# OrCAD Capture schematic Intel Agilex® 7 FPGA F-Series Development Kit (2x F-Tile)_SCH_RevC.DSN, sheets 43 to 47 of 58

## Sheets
43 PG47 VCC Phase 1: size C
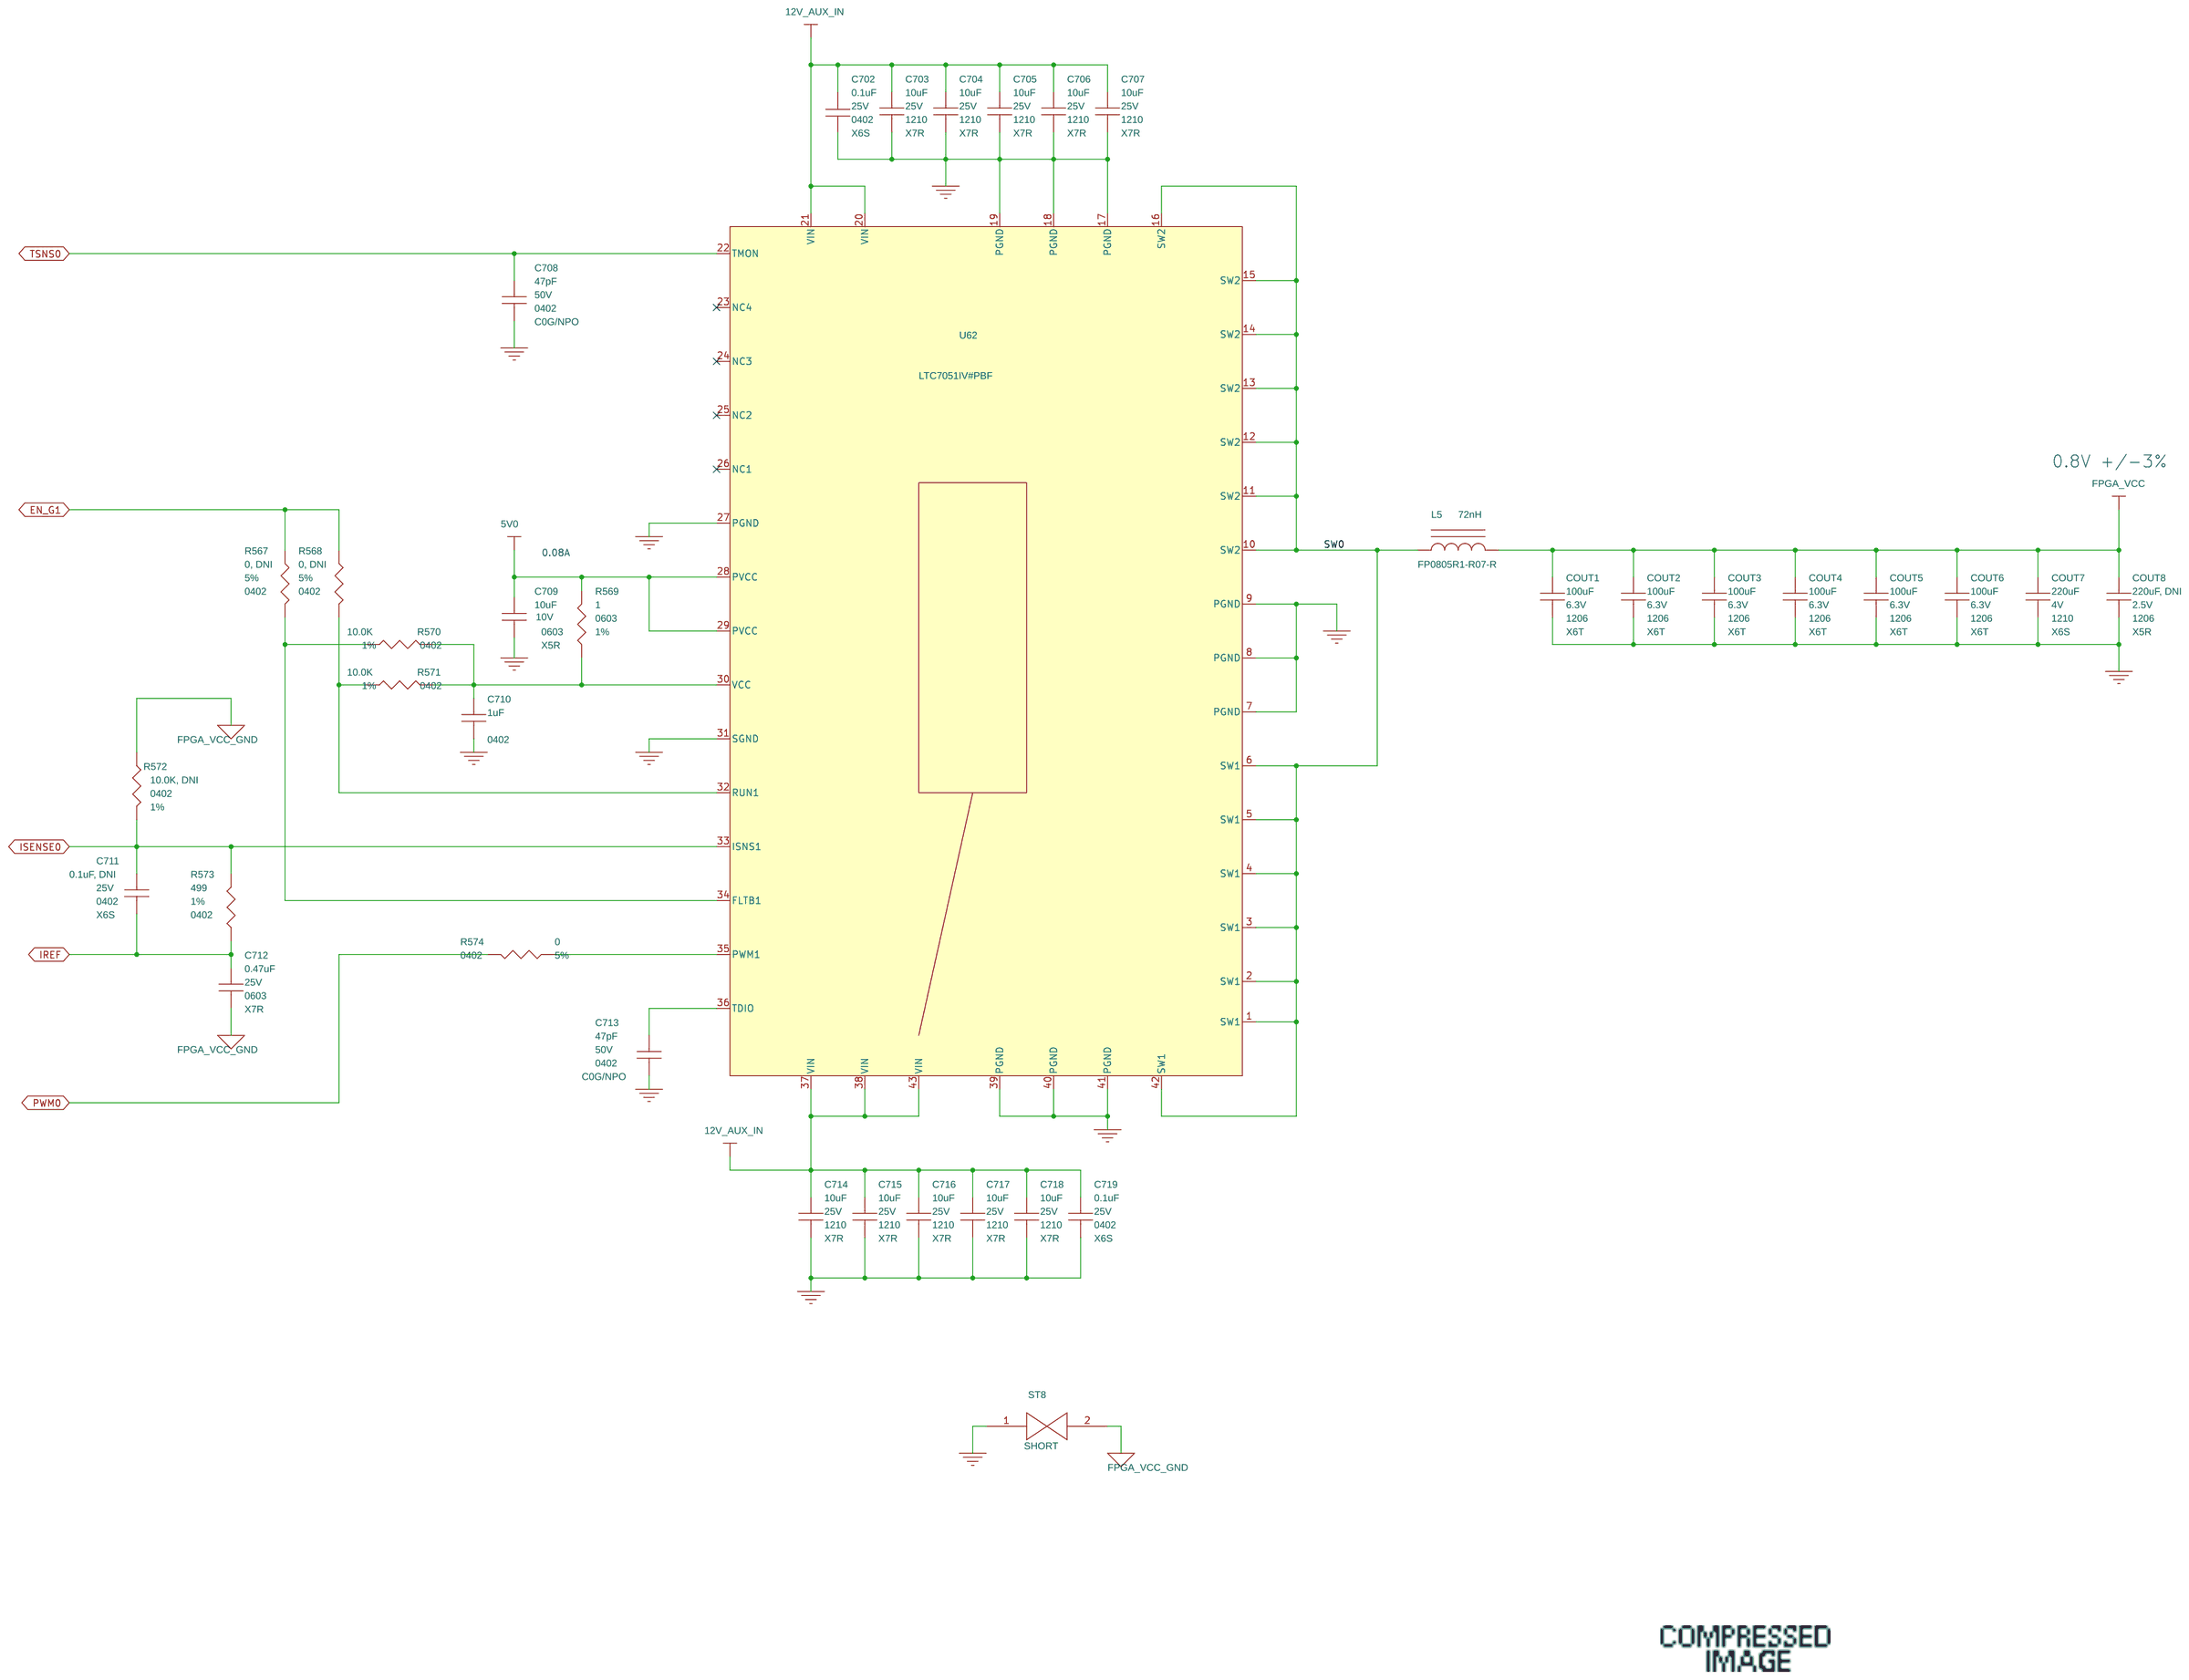
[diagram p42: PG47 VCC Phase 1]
44 PG48 VCC Phase 2: size C
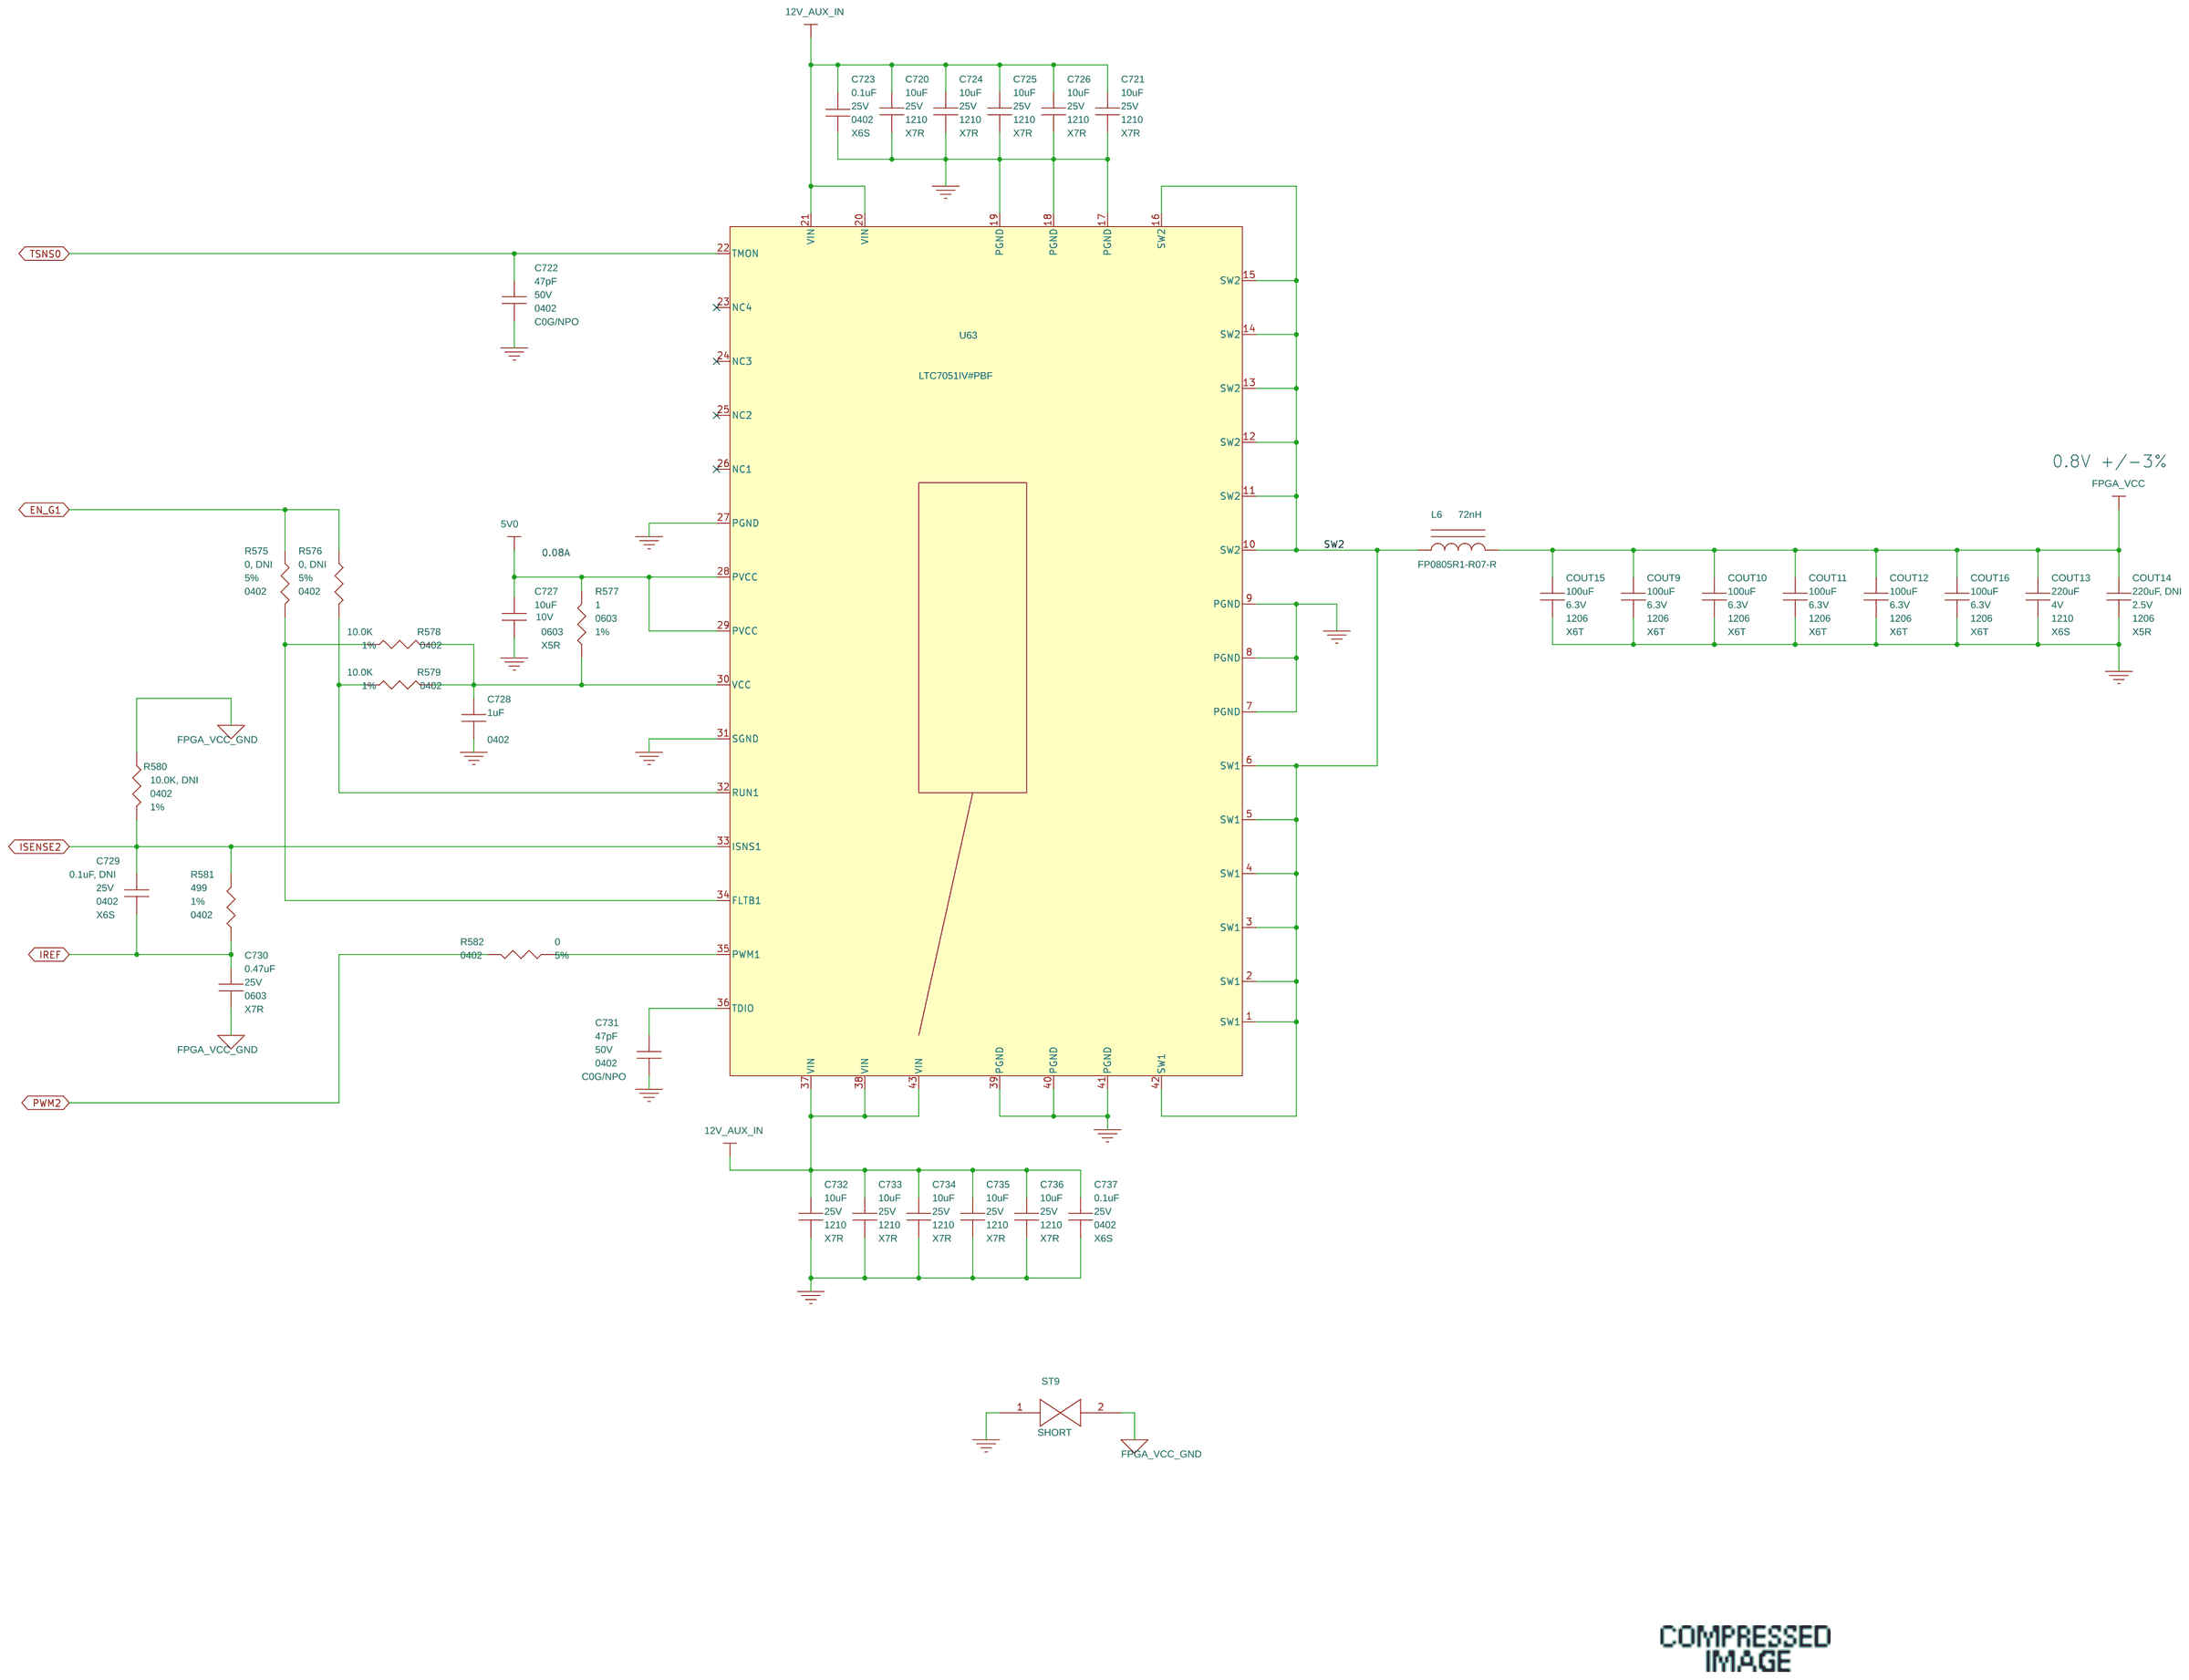
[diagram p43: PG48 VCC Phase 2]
45 PG49 VCC Phase 3: size C
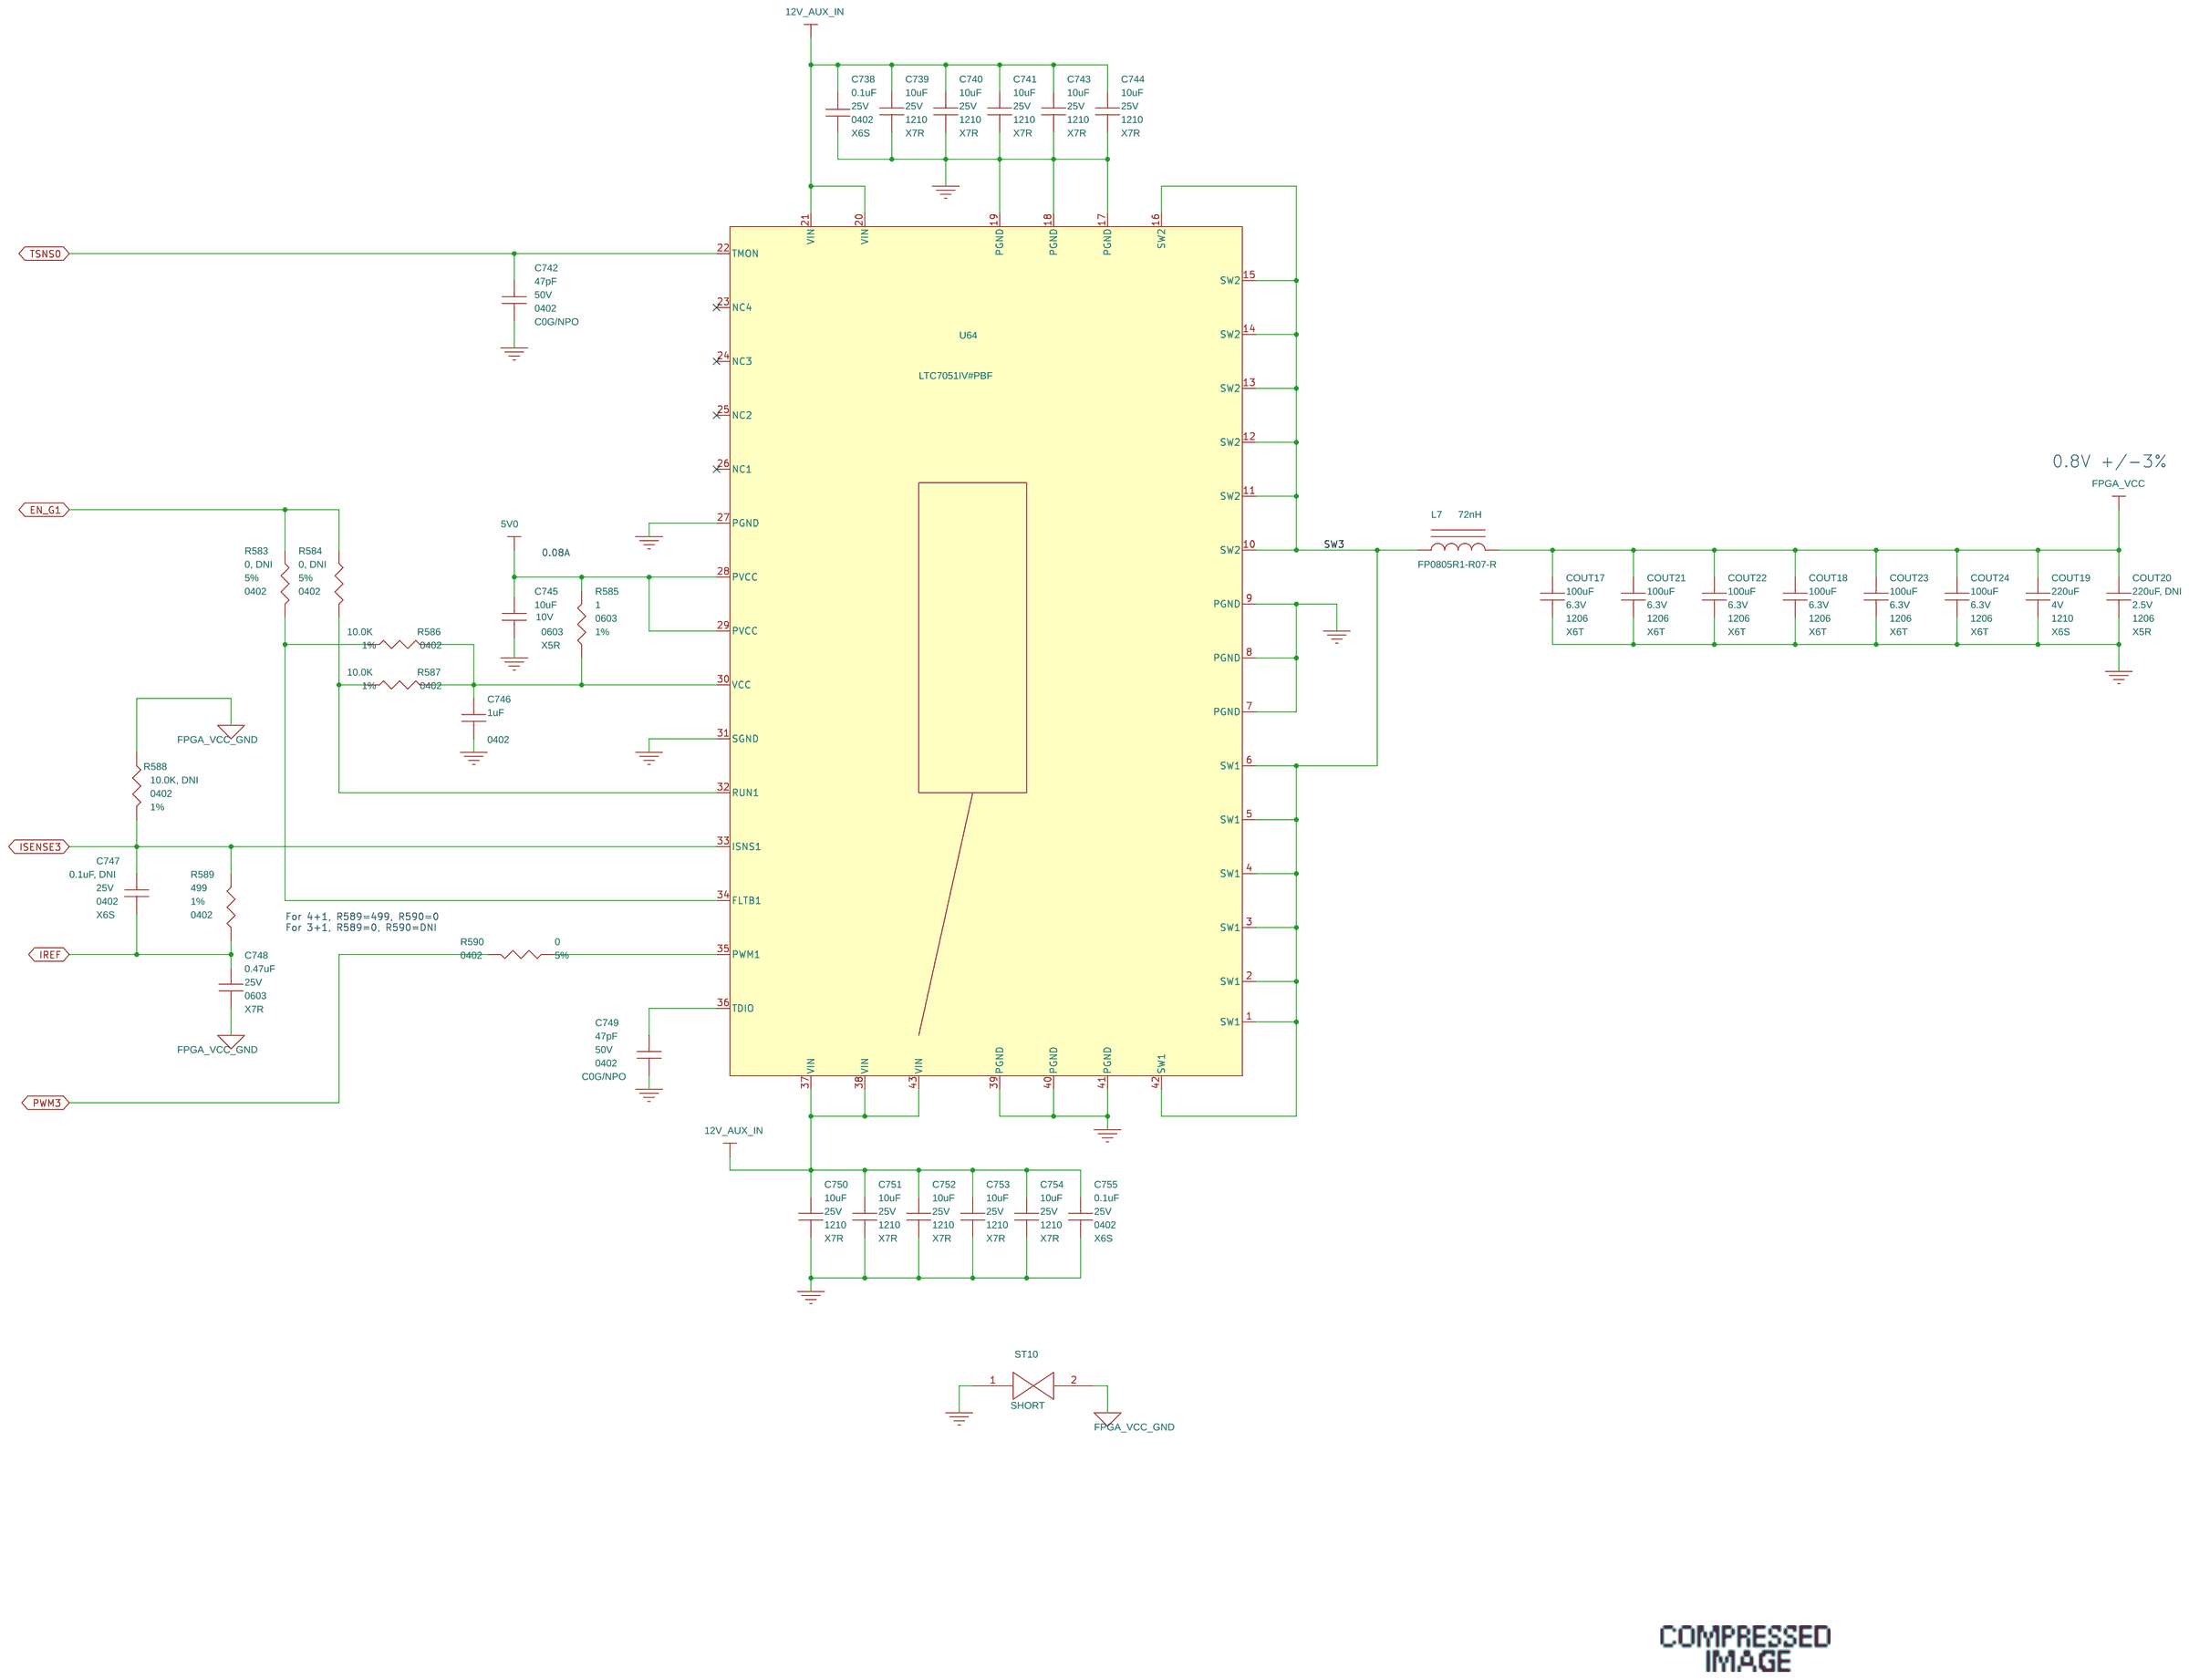
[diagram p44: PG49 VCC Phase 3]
46 PG50 VCC Phase 4: size C
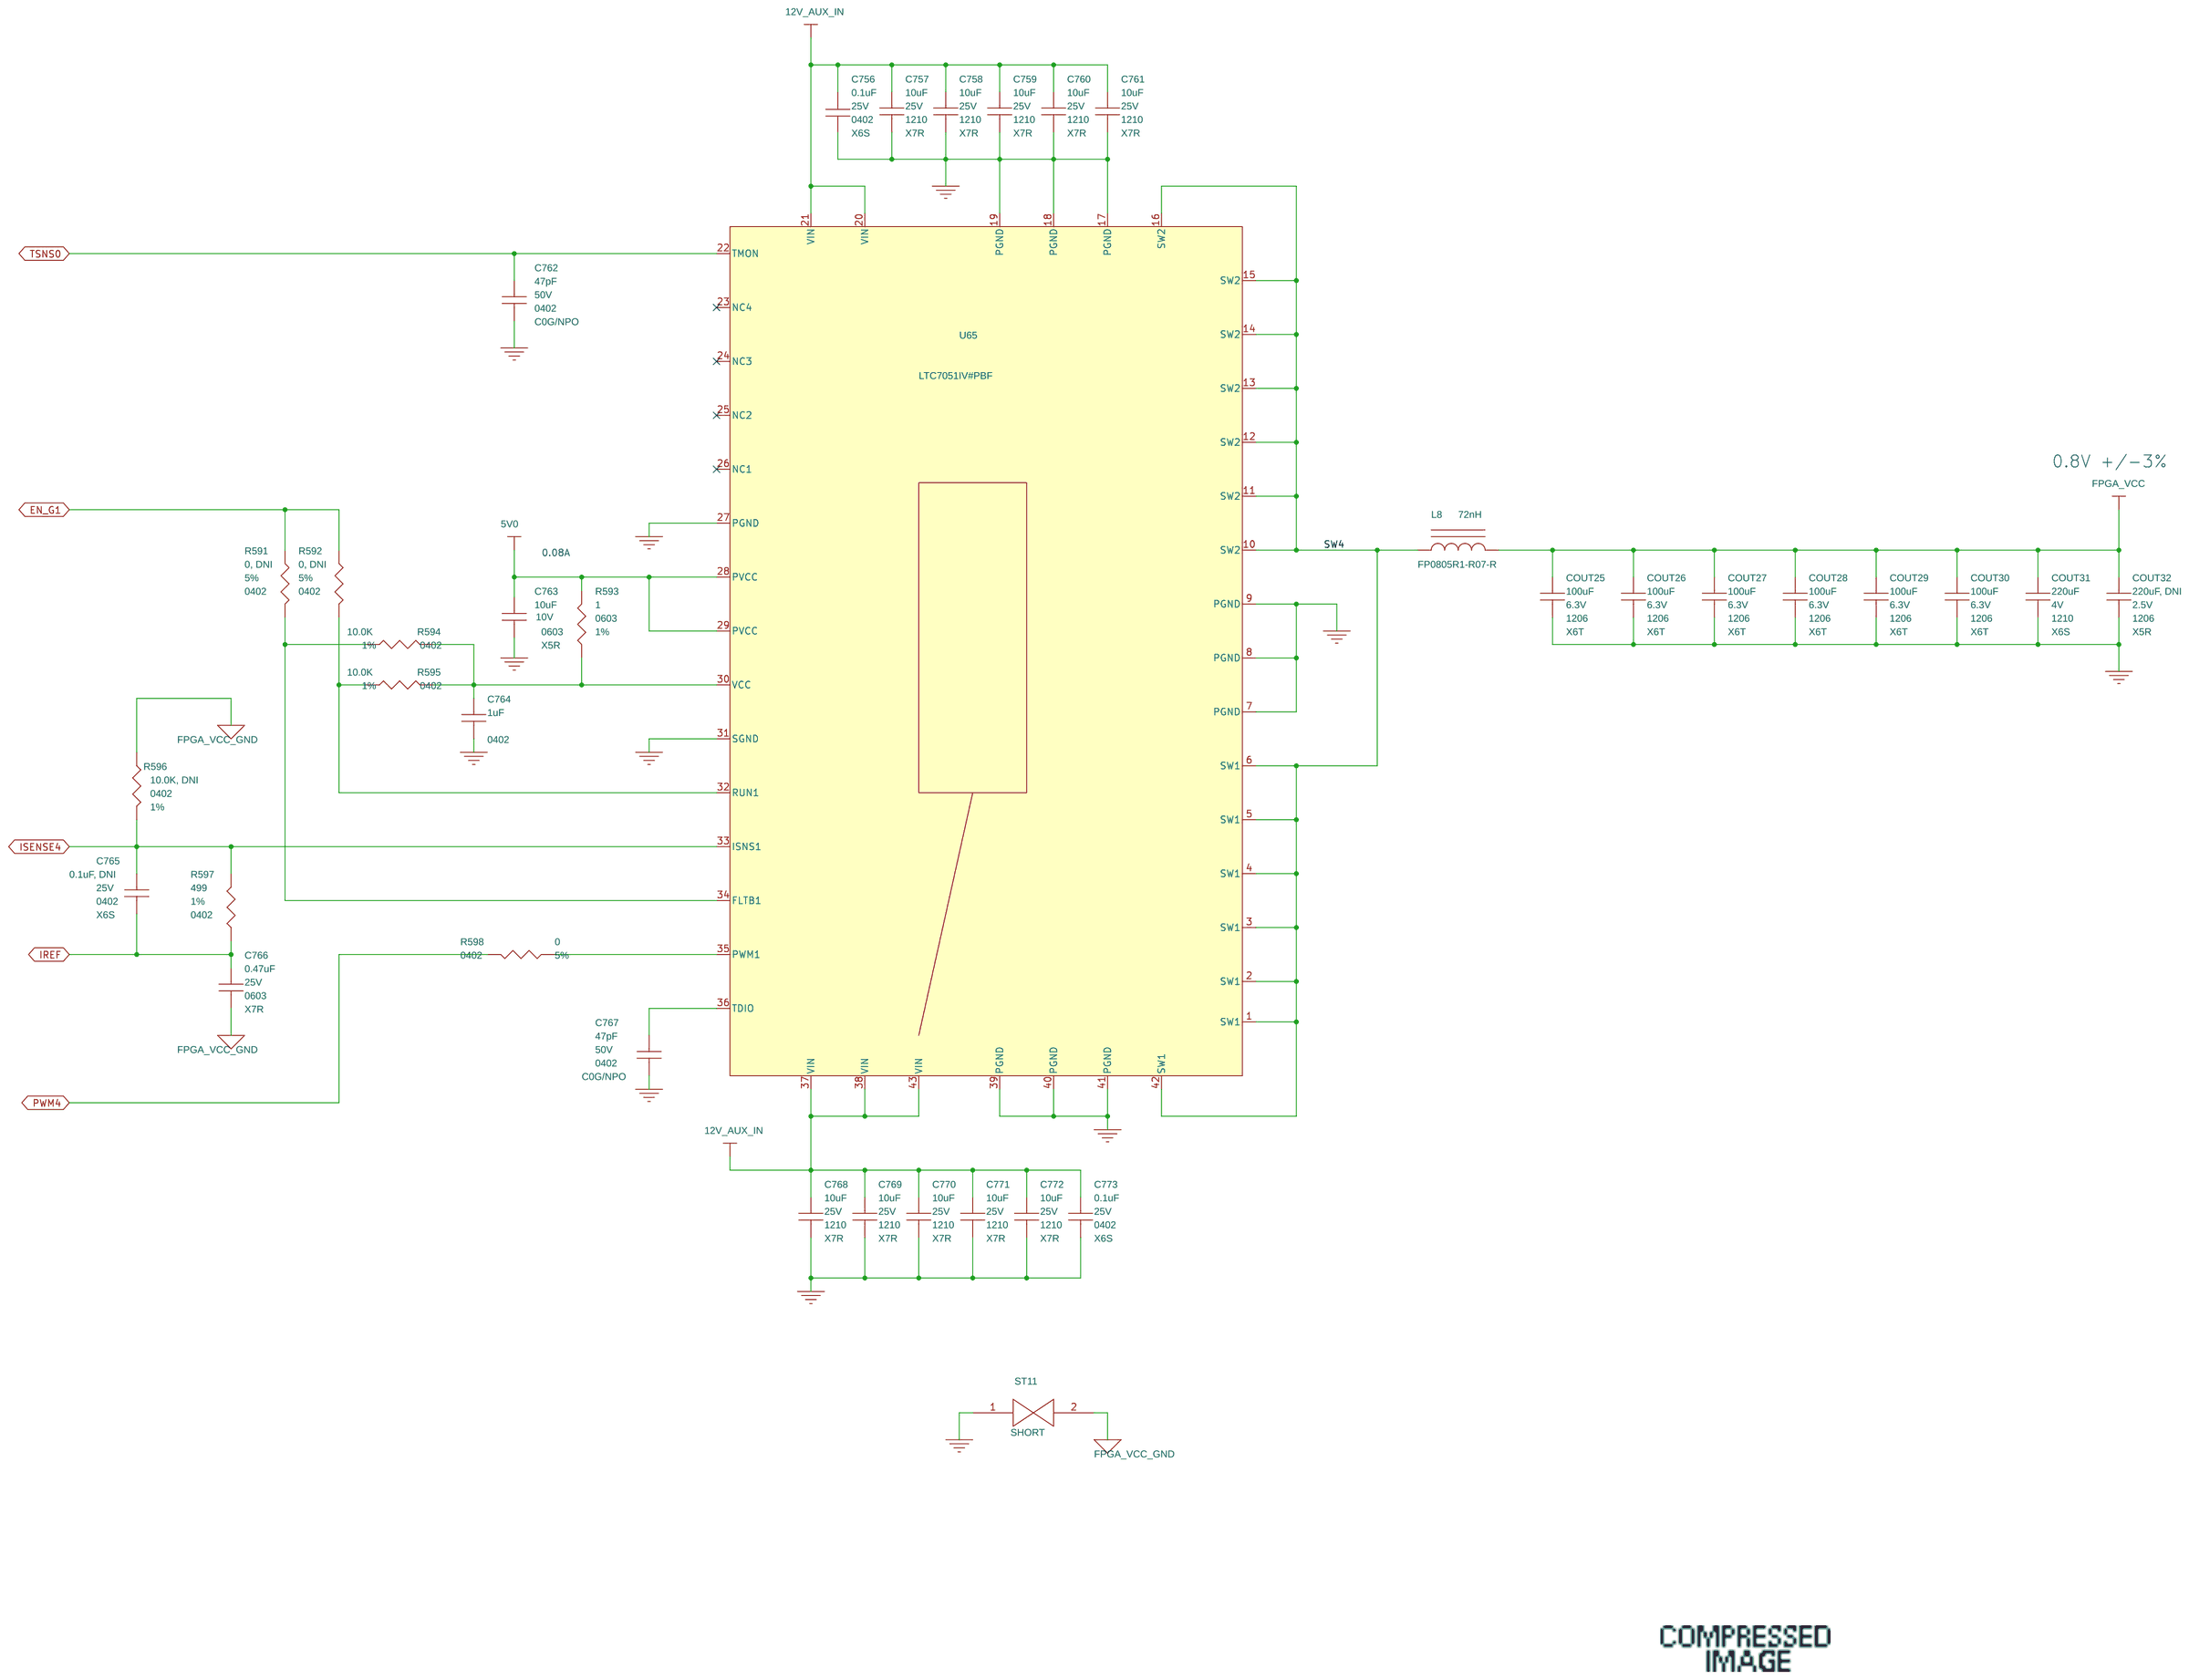
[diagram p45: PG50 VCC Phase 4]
47 PG51 VCC_HSSI_GXF Phase 5: size C
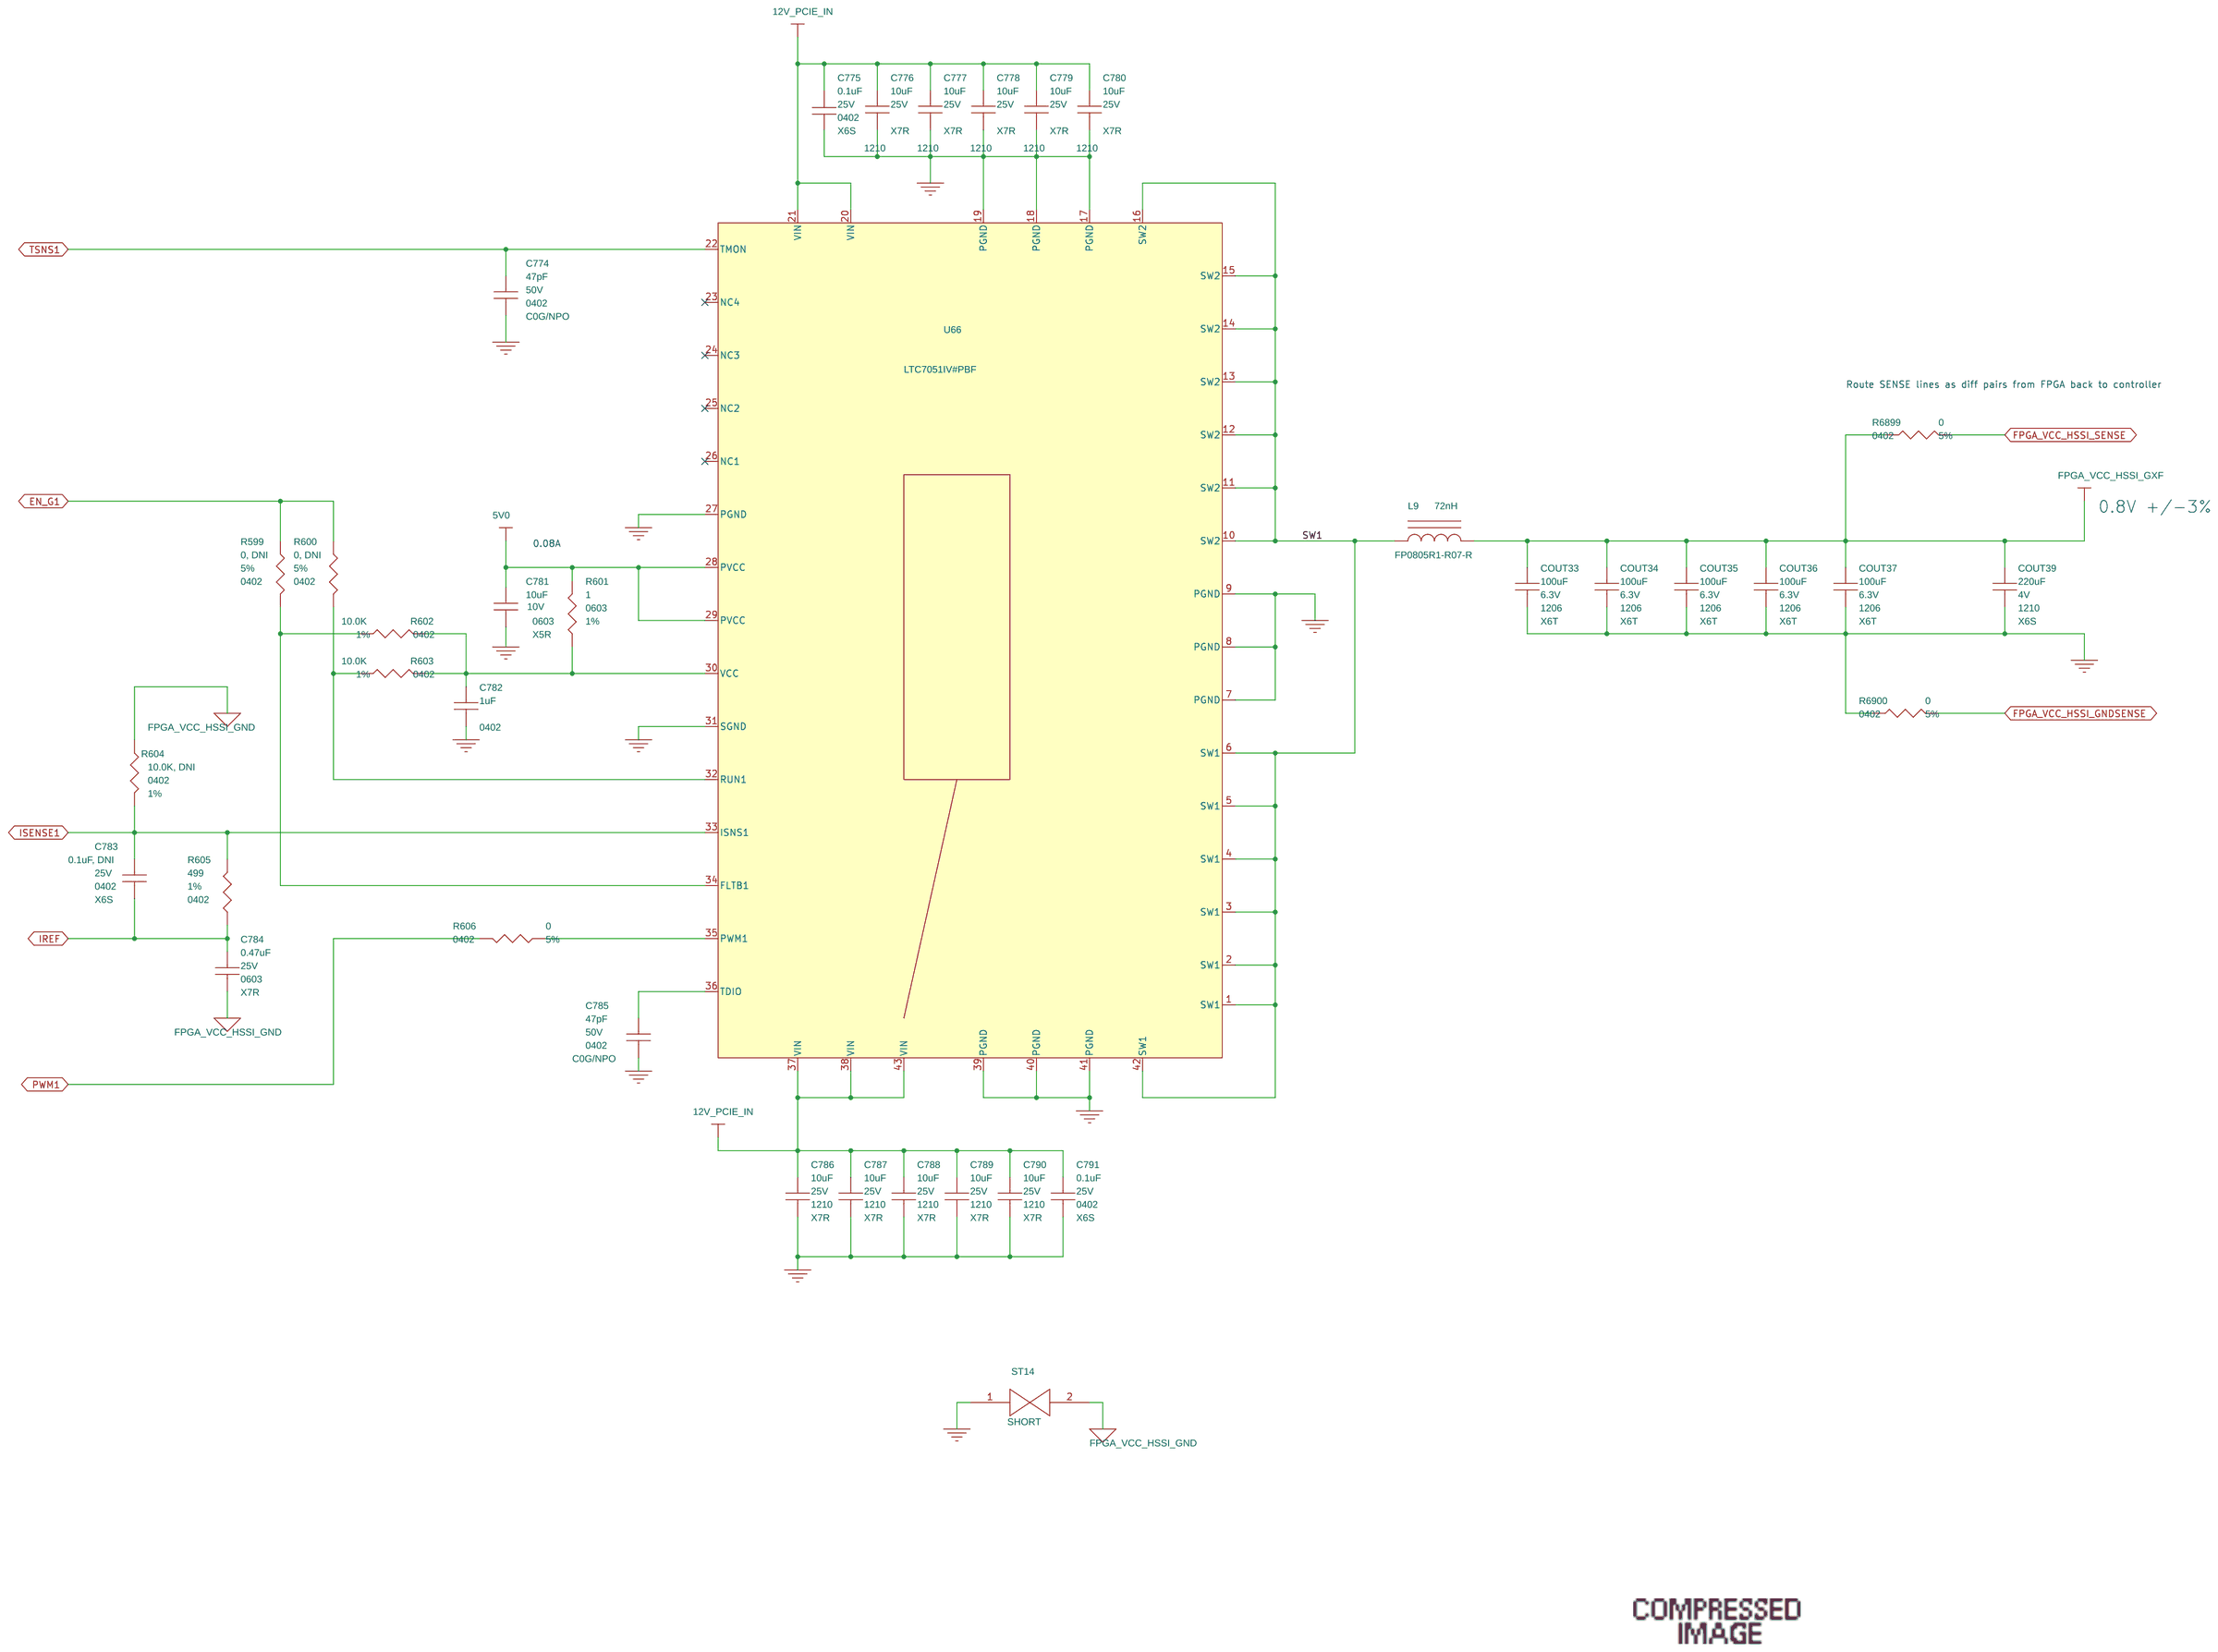
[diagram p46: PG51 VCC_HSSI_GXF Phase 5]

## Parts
sheet PG47 VCC Phase 1
C702  0.1uF  [0402]
C703  10uF  [1210_H2p2mm]
C704  10uF  [1210_H2p2mm]
C705  10uF  [1210_H2p2mm]
C706  10uF  [1210_H2p2mm]
C707  10uF  [1210_H2p2mm]
C708  47pF  [0402]
C709  10uF  [0603]
C710  1uF  [0402]
C711  0.1uF, DNI  [0402]
C712  0.47uF  [0603]
C713  47pF  [0402]
C714  10uF  [1210_H2p2mm]
C715  10uF  [1210_H2p2mm]
C716  10uF  [1210_H2p2mm]
C717  10uF  [1210_H2p2mm]
C718  10uF  [1210_H2p2mm]
C719  0.1uF  [0402]
COUT1  100uF  [1206]
COUT2  100uF  [1206]
COUT3  100uF  [1206]
COUT4  100uF  [1206]
COUT5  100uF  [1206]
COUT6  100uF  [1206]
COUT7  220uF  [1210]
COUT8  220uF, DNI  [1206]
L5  72nH  [Eaton_FP0805R1-R07-R]
R567  0, DNI  [0402]
R568  0, DNI  [0402]
R569  1  [0603]
R570  10.0K  [0402]
R571  10.0K  [0402]
R572  10.0K, DNI  [0402]
R573  499  [0402]
R574  0  [0402]
ST8  SHORT  [SHORT]
U62  LTC7051IV#PBF  [LTC-LQFN-42-1571]
sheet PG48 VCC Phase 2
C720  10uF  [1210_H2p2mm]
C721  10uF  [1210_H2p2mm]
C722  47pF  [0402]
C723  0.1uF  [0402]
C724  10uF  [1210_H2p2mm]
C725  10uF  [1210_H2p2mm]
C726  10uF  [1210_H2p2mm]
C727  10uF  [0603]
C728  1uF  [0402]
C729  0.1uF, DNI  [0402]
C730  0.47uF  [0603]
C731  47pF  [0402]
C732  10uF  [1210_H2p2mm]
C733  10uF  [1210_H2p2mm]
C734  10uF  [1210_H2p2mm]
C735  10uF  [1210_H2p2mm]
C736  10uF  [1210_H2p2mm]
C737  0.1uF  [0402]
COUT9  100uF  [1206]
COUT10  100uF  [1206]
COUT11  100uF  [1206]
COUT12  100uF  [1206]
COUT13  220uF  [1210]
COUT14  220uF, DNI  [1206]
COUT15  100uF  [1206]
COUT16  100uF  [1206]
L6  72nH  [Eaton_FP0805R1-R07-R]
R575  0, DNI  [0402]
R576  0, DNI  [0402]
R577  1  [0603]
R578  10.0K  [0402]
R579  10.0K  [0402]
R580  10.0K, DNI  [0402]
R581  499  [0402]
R582  0  [0402]
ST9  SHORT  [SHORT]
U63  LTC7051IV#PBF  [LTC-LQFN-42-1571]
sheet PG49 VCC Phase 3
C738  0.1uF  [0402]
C739  10uF  [1210_H2p2mm]
C740  10uF  [1210_H2p2mm]
C741  10uF  [1210_H2p2mm]
C742  47pF  [0402]
C743  10uF  [1210_H2p2mm]
C744  10uF  [1210_H2p2mm]
C745  10uF  [0603]
C746  1uF  [0402]
C747  0.1uF, DNI  [0402]
C748  0.47uF  [0603]
C749  47pF  [0402]
C750  10uF  [1210_H2p2mm]
C751  10uF  [1210_H2p2mm]
C752  10uF  [1210_H2p2mm]
C753  10uF  [1210_H2p2mm]
C754  10uF  [1210_H2p2mm]
C755  0.1uF  [0402]
COUT17  100uF  [1206]
COUT18  100uF  [1206]
COUT19  220uF  [1210]
COUT20  220uF, DNI  [1206]
COUT21  100uF  [1206]
COUT22  100uF  [1206]
COUT23  100uF  [1206]
COUT24  100uF  [1206]
L7  72nH  [Eaton_FP0805R1-R07-R]
R583  0, DNI  [0402]
R584  0, DNI  [0402]
R585  1  [0603]
R586  10.0K  [0402]
R587  10.0K  [0402]
R588  10.0K, DNI  [0402]
R589  499  [0402]
R590  0  [0402]
ST10  SHORT  [SHORT]
U64  LTC7051IV#PBF  [LTC-LQFN-42-1571]
sheet PG50 VCC Phase 4
C756  0.1uF  [0402]
C757  10uF  [1210_H2p2mm]
C758  10uF  [1210_H2p2mm]
C759  10uF  [1210_H2p2mm]
C760  10uF  [1210_H2p2mm]
C761  10uF  [1210_H2p2mm]
C762  47pF  [0402]
C763  10uF  [0603]
C764  1uF  [0402]
C765  0.1uF, DNI  [0402]
C766  0.47uF  [0603]
C767  47pF  [0402]
C768  10uF  [1210_H2p2mm]
C769  10uF  [1210_H2p2mm]
C770  10uF  [1210_H2p2mm]
C771  10uF  [1210_H2p2mm]
C772  10uF  [1210_H2p2mm]
C773  0.1uF  [0402]
COUT25  100uF  [1206]
COUT26  100uF  [1206]
COUT27  100uF  [1206]
COUT28  100uF  [1206]
COUT29  100uF  [1206]
COUT30  100uF  [1206]
COUT31  220uF  [1210]
COUT32  220uF, DNI  [1206]
L8  72nH  [Eaton_FP0805R1-R07-R]
R591  0, DNI  [0402]
R592  0, DNI  [0402]
R593  1  [0603]
R594  10.0K  [0402]
R595  10.0K  [0402]
R596  10.0K, DNI  [0402]
R597  499  [0402]
R598  0  [0402]
ST11  SHORT  [SHORT]
U65  LTC7051IV#PBF  [LTC-LQFN-42-1571]
sheet PG51 VCC_HSSI_GXF Phase 5
C774  47pF  [0402]
C775  0.1uF  [0402]
C776  10uF  [1210_H2p2mm]
C777  10uF  [1210_H2p2mm]
C778  10uF  [1210_H2p2mm]
C779  10uF  [1210_H2p2mm]
C780  10uF  [1210_H2p2mm]
C781  10uF  [0603]
C782  1uF  [0402]
C783  0.1uF, DNI  [0402]
C784  0.47uF  [0603]
C785  47pF  [0402]
C786  10uF  [1210_H2p2mm]
C787  10uF  [1210_H2p2mm]
C788  10uF  [1210_H2p2mm]
C789  10uF  [1210_H2p2mm]
C790  10uF  [1210_H2p2mm]
C791  0.1uF  [0402]
COUT33  100uF  [1206]
COUT34  100uF  [1206]
COUT35  100uF  [1206]
COUT36  100uF  [1206]
COUT37  100uF  [1206]
COUT39  220uF  [1210]
L9  72nH  [Eaton_FP0805R1-R07-R]
R599  0, DNI  [0402]
R600  0, DNI  [0402]
R601  1  [0603]
R602  10.0K  [0402]
R603  10.0K  [0402]
R604  10.0K, DNI  [0402]
R605  499  [0402]
R606  0  [0402]
R6899  0  [0402]
R6900  0  [0402]
ST14  SHORT  [SHORT]
U66  LTC7051IV#PBF  [LTC-LQFN-42-1571]

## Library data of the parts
C702 C723 C738 C756 C775 = CAP: CAP CER 0.1UF 25V X6S 0402; Dielectric: X6S; IPN: K19434-001; Item Num: K19434-001; LIFECYCLE_PHASE: Active; Lead Free Status: Lead Free; MFR_LIFECYCLE: Active; Manufacturer: Murata; Manufacturer Part Num: GRM155C81E104KA12D; Num Pins: 2; PART_SUBCLASS: CAPACITORS; Part Class: CAPACITORS; RATED_VOLTAGE: 25V; RoHS Compliant: RoHS Compliant; Temperature Coefficient: X6S; Tolerance: 10%
C703-C707 C714-C718 C720 C721 C724-C726 C732-C736 C739-C741 C743 C744 C750-C754 C757-C761 C768-C772 C776-C780 C786-C790 = CAP_10uF_+_-10%_25V_1210: CAP - CER, 10UF, 25V, 10%, X7R, 1210; Agile Part Description: CAP - CER, 10UF, 25V, 10%, X7R, 1210; Item Num: G10603-003; Manufacturer Part Num: GRM32DR71E106KA12L; Package: 1210; Temperature Coefficient: X7R; Voltage: 25V
C708 C722 C742 C762 C774 = CAP: CAP CER 47PF 50V C0G/NP0 0402; CLASS: DISCRETE; Dielectric Type: C0G; FPLIST: CC0603N,CC0603L,CC0603M; IPN: xxxxxx-xxx; Item Num: K19455-001; Manufacturer: Murata; Manufacturer PN: GRM1555C1H470FA01D; Manufacturer Part Num: GRM1555C1H470FA01D; PART_NUMBER: 150-0054; Rated Voltage: 50V; Temperature Coefficient: C0G/NPO; Tolerance: 5%
C709 C727 C745 C763 C781 = CAP: CAP 10UF 10VDC X5R +/-15% 0603; CLASS: DISCRETE; Dielectric Type: X5R; FPLIST: CC0603N,CC0603L,CC0603M; IPN: xxxxxx-xxx; Item Num: J60031-001; Manufacturer: Murata; Manufacturer PN: 0603ZD106KAT2A; Manufacturer Part Num: GRM188R61A106KE69D; PART_NUMBER: 150-0576; Rated Voltage: 10V; Tolerance: 10%
C710 C728 C746 C764 C782 = CAP: CAP CER 1UF 25V X6S 0402; Item Num: H81594-001; Lead Free Status: Yes; Manufacturer: Murata; Manufacturer Part Num: GRM155C81E105KE11D; Num Pins: 2; Part Class: CAPACITORS; RATED_VOLTAGE: 25V; RoHS Compliant: Yes; Temperature Coefficient: X6S
C711 C729 C747 C765 C783 = CAP: CAP CER 0.1UF 25V X6S 0402; CAPACITANCE: 0.1uF; Dielectric: X6S; IPN: K19434-001; Item Num: K19434-001; LIFECYCLE_PHASE: Active; Lead Free Status: Lead Free; MFR_LIFECYCLE: Active; Manufacturer: Murata; Manufacturer Part Num: GRM155C81E104KA12D; PART_SUBCLASS: CAPACITORS; Part Class: CAPACITORS; RATED_VOLTAGE: 25V; RoHS Compliant: RoHS Compliant; Temperature Coefficient: X6S; Tolerance: 10%; Voltage: 25V
C712 C730 C748 C766 C784 = CAP: 0.47µF ±10% 25V Ceramic Capacitor X7R 0603; Item Num: G32675-001; LIFECYCLE_PHASE: Active; Lead Free Status: Lead Free; MFR_LIFECYCLE: Active; Manufacturer: Murata; Manufacturer Part Num: GRM188R71E474KA12D; Num Pins: 2; PART_SUBCLASS: CAPACITORS; Part Class: CAPACITORS; RATED_VOLTAGE: 25V; Rated Voltage: 25V; RoHS Compliant: RoHS Compliant; Temperature Coefficient: X7R; Tolerance: 10%
C713 C731 C749 C767 C785 = CAP: CAP CER 47PF 50V C0G/NP0 0402; CLASS: DISCRETE; Dielectric Type: C0G; FPLIST: CC0603N,CC0603L,CC0603M; IPN: xxxxxx-xxx; Item Num: K19455-001; Manufacturer: Murata; Manufacturer PN: GRM1555C1H470FA01D; Manufacturer Part Num: GRM1555C1H470FA01D; PART_NUMBER: 150-0054; Package Size: 0603; Rated Voltage: 50V; Temperature Coefficient: C0G/NPO; Tolerance: 5%
C719 C737 C755 C773 C791 = CAP: CAP CER 0.1UF 25V X6S 0402; Dielectric: X6S; IPN: K19434-001; Item Num: K19434-001; LIFECYCLE_PHASE: Active; Lead Free Status: Lead Free; MFR_LIFECYCLE: Active; Manufacturer: Murata; Manufacturer Part Num: GRM155C81E104KA12D; PART_SUBCLASS: CAPACITORS; Part Class: CAPACITORS; RATED_VOLTAGE: 25V; RoHS Compliant: RoHS Compliant; Temperature Coefficient: X6S; Tolerance: 10%; Voltage: 25V
COUT1-COUT6 COUT9-COUT12 COUT15-COUT18 COUT21-COUT30 COUT33-COUT37 = CAP: CAP CER 100UF 6.3V X6T 1206; CLASS: DISCRETE; Dielectric Type: X6T; Item Num: H65271-004; LIFECYCLE_PHASE: Active; Lead Free Status: Lead Free; MFR_LIFECYCLE: Active; Manufacturer: Murata; Manufacturer PN: GRM31CD80J107ME39L; Manufacturer Part Num: GRM31CR60J107ME39L; Num Pins: 2; PART_SUBCLASS: CAPACITORS; RATED_VOLTAGE: 6.3V; Rated Voltage: 6.3V; RoHS Compliant: RoHS Compliant; Temperature Coefficient: X6T; Tolerance: 20%; Working Voltage: 6.3V
COUT7 COUT13 COUT19 COUT31 COUT39 = CAP: CAP CER 220UF 4V X6S 1210; CLASS: DISCRETE; Dielectric Type: X6S; IPN: xxxxxx-xxx; Item Num: D38464-012; Manufacturer: Murata; Manufacturer PN: GRM32EC80G227ME05L; Manufacturer Part Num: GRM32EC80G227ME05L; Rated Voltage: 4V; Temperature Coefficient: X6S; Tolerance: 20%; Working Voltage: 4V
COUT8 COUT14 COUT20 COUT32 = CAP: CAP CER 220UF 4V X6S 1206; CLASS: DISCRETE; Dielectric Type: X5R; IPN: C34226-008; Item Num: C34226-008; Manufacturer: Taiyo Yuden; Manufacturer PN: PMK316BBJ227ML-T; Manufacturer Part Num: PMK316BBJ227ML-T; Rated Voltage: 2.5V; Temperature Coefficient: X5R; Tolerance: 20%; Working Voltage: 2.5V
L5-L9 = INDUCTOR_IRON_ALT: IND.,72nH,Un-shielded Inductor,10%,65A,0.17m OHMS,7.62mm X 7.49mm; CLASS: DISCRETE; IPN: M52287-001; Item Num: M52287-001; Manufacturer: EATON; Manufacturer PN: FP0805R1-R07-R; Manufacturer Part Num: FP0805R1-R07-R; Package Size: 7.62mm x 7.49mm; Tolerance: 10%
R567 R568 R575 R576 R583 R584 R591 R592 R599 R600 = RESISTOR: RES ZERO OHM 1/16W 5% 0402 SMD; IPN: A93549-001; Item Num: A93549-001; Lead Free Status: Yes; Manufacturer: Yageo; Manufacturer Part Num: RC0402JR-070RL; Num Pins: 2; Part Class: RESISTORS; RoHS Compliant: Yes; Tolerance: 5%
R569 R577 R585 R593 R601 = RES: RES.,1 OHM,1%,1/10W,0603; CLASS: DISCRETE; FPLIST: CR0603N,CR0603L,CR0603M; IPN: xxxxxx-xxx; Item Num: A93550-324; Manufacturer: YAGEO; Manufacturer PN: RC0603FR-071RL; Manufacturer Part Num: RC0603FR-071RL; PART_NUMBER: 100-0163; Rated Power: 1/10W; Temperature Coefficient: 200ppm/C; Tolerance: 1%
R570 R571 R578 R579 R586 R587 R594 R595 R602 R603 = RESISTOR: RES,10.0K OHMS,1.0%,1/16W, 0402; AGILE_LINK: http://sj-agile9app/Agile/PLMServlet?action=OpenEmailObject&classid=10000&objid=146548997; Item Num: K28115-001; LIFECYCLE_PHASE: Active; Lead Free Status: Yes; MFR_LIFECYCLE: Active; Manufacturer: Panasonic; Manufacturer Part Num: ERJ-2RKF1002X; Num Pins: 2; PART_SUBCLASS: RESISTORS; POWER: 1/16W; RoHS Compliant: Yes; TOLERANCE: 1%
R572 R580 R588 R596 R604 = RESISTOR: RES,10.0K OHMS,1.0%,1/16W, 0402; AGILE_LINK: http://sj-agile9app/Agile/PLMServlet?action=OpenEmailObject&classid=10000&objid=146548997; Item Num: K28115-001; LIFECYCLE_PHASE: Active; Lead Free Status: Yes; MFR_LIFECYCLE: Active; Manufacturer: Panasonic; Manufacturer Part Num: ERJ-2RKF1002X; Num Pins: 2; PART_SUBCLASS: RESISTORS; POWER: 1/16W; RESISTANCE: 10.0K; RoHS Compliant: Yes; TOLERANCE: 1%
R573 R581 R589 R597 R605 = RES: RES 499 OHM 1/16W 1% 0402 SMD; Item Num: A93548-094; Manufacturer: Yageo; Manufacturer Part Num: RC0402FR-07499RL; Num Pins: 2; Part Class: RESISTORS; Tolerance: 1%
R574 R582 R6899 R6900 = RESISTOR: RES ZERO OHM 1/16W 5% 0402 SMD; Item Num: A93549-001; Lead Free Status: No; Manufacturer: Yageo; Manufacturer Part Num: RC0402JR-070RL; Num Pins: 2; Part Class: RESISTORS; RoHS Compliant: Yes; Tolerance: 5%
ST8-ST11 ST14 = SHORT
U62-U66 = LTC7501-LGA_1: IC,Smart single 60A DrMOS,43-PIN LQFN; CLASS: IC; IPN: xxxxxx-xxx; Item Num: K82945-001; Manufacturer: ANALOG DEVICES INC.; Manufacturer Part Num: LTC7051AV#PBF; Package Type: 43-PIN LGA
R590 R598 R606 = RESISTOR: RES ZERO OHM 1/16W 5% 0402 SMD; Item Num: A93549-001; Lead Free Status: Yes; Manufacturer: Yageo; Manufacturer Part Num: RC0402JR-070RL; Num Pins: 2; Part Class: RESISTORS; RoHS Compliant: Yes; Tolerance: 5%

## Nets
5V0: C709.1 C727.1 C745.1 C763.1 C781.1 R569.1 R577.1 R585.1 R593.1 R601.1 U62.28(PVCC) U62.29(PVCC) U63.28(PVCC) U63.29(PVCC) U64.28(PVCC) U64.29(PVCC) U65.28(PVCC) U65.29(PVCC) U66.28(PVCC) U66.29(PVCC) ; also on sheet 36 58
12V_AUX_IN: C702.2 C703.1 C704.1 C705.1 C706.1 C707.1 C714.1 C715.1 C716.1 C717.1 C718.1 C719.1 C720.1 C721.1 C723.2 C724.1 C725.1 C726.1 C732.1 C733.1 C734.1 C735.1 C736.1 C737.1 C738.2 C739.1 C740.1 C741.1 C743.1 C744.1 C750.1 C751.1 C752.1 C753.1 C754.1 C755.1 C756.2 C757.1 C758.1 C759.1 C760.1 C761.1 C768.1 C769.1 C770.1 C771.1 C772.1 C773.1 U62.20(VIN) U62.21(VIN) U62.37(VIN) U62.38(VIN) U62.43(VIN) U63.20(VIN) U63.21(VIN) U63.37(VIN) U63.38(VIN) U63.43(VIN) U64.20(VIN) U64.21(VIN) U64.37(VIN) U64.38(VIN) U64.43(VIN) U65.20(VIN) U65.21(VIN) U65.37(VIN) U65.38(VIN) U65.43(VIN) ; also on sheet 10 40 42 58
12V_PCIE_IN: C775.2 C776.1 C777.1 C778.1 C779.1 C780.1 C786.1 C787.1 C788.1 C789.1 C790.1 C791.1 U66.20(VIN) U66.21(VIN) U66.37(VIN) U66.38(VIN) U66.43(VIN) ; also on sheet 28 40 41 49 50 55 56
GND: C702.1 C703.2 C704.2 C705.2 C706.2 C707.2 C708.2 C709.2 C710.2 C713.2 C714.2 C715.2 C716.2 C717.2 C718.2 C719.2 C720.2 C721.2 C722.2 C723.1 C724.2 C725.2 C726.2 C727.2 C728.2 C731.2 C732.2 C733.2 C734.2 C735.2 C736.2 C737.2 C738.1 C739.2 C740.2 C741.2 C742.2 C743.2 C744.2 C745.2 C746.2 C749.2 C750.2 C751.2 C752.2 C753.2 C754.2 C755.2 C756.1 C757.2 C758.2 C759.2 C760.2 C761.2 C762.2 C763.2 C764.2 C767.2 C768.2 C769.2 C770.2 C771.2 C772.2 C773.2 C774.2 C775.1 C776.2 C777.2 C778.2 C779.2 C780.2 C781.2 C782.2 C785.2 C786.2 C787.2 C788.2 C789.2 C790.2 C791.2 COUT1.2 COUT2.2 COUT3.2 COUT4.2 COUT5.2 COUT6.2 COUT7.2 COUT8.2 COUT9.2 COUT10.2 COUT11.2 COUT12.2 COUT13.2 COUT14.2 COUT15.2 COUT16.2 COUT17.2 COUT18.2 COUT19.2 COUT20.2 COUT21.2 COUT22.2 COUT23.2 COUT24.2 COUT25.2 COUT26.2 COUT27.2 COUT28.2 COUT29.2 COUT30.2 COUT31.2 COUT32.2 COUT33.2 COUT34.2 COUT35.2 COUT36.2 COUT37.2 COUT39.2 R6900.1 ST8.1 ST9.1 ST10.1 ST11.1 ST14.1 U62.7(PGND) U62.8(PGND) U62.9(PGND) U62.17(PGND) U62.18(PGND) U62.19(PGND) U62.27(PGND) U62.31(SGND) U62.39(PGND) U62.40(PGND) U62.41(PGND) U63.7(PGND) U63.8(PGND) U63.9(PGND) U63.17(PGND) U63.18(PGND) U63.19(PGND) U63.27(PGND) U63.31(SGND) U63.39(PGND) U63.40(PGND) U63.41(PGND) U64.7(PGND) U64.8(PGND) U64.9(PGND) U64.17(PGND) U64.18(PGND) U64.19(PGND) U64.27(PGND) U64.31(SGND) U64.39(PGND) U64.40(PGND) U64.41(PGND) U65.7(PGND) U65.8(PGND) U65.9(PGND) U65.17(PGND) U65.18(PGND) U65.19(PGND) U65.27(PGND) U65.31(SGND) U65.39(PGND) U65.40(PGND) U65.41(PGND) U66.7(PGND) U66.8(PGND) U66.9(PGND) U66.17(PGND) U66.18(PGND) U66.19(PGND) U66.27(PGND) U66.31(SGND) U66.39(PGND) U66.40(PGND) U66.41(PGND) ; also on sheet 8 9 10 11 12 13 15 16 19 20 21 22 23 24 25 26 27 28 29 30 31 32 33 34 35 36 37 38 39 40 41 42 48 49 50 51 52 53 54 55 56 58
EN_G1: R567.1 R568.1 R575.1 R576.1 R583.1 R584.1 R591.1 R592.1 R599.1 R600.1 ; also on sheet 10 42 48 49
FPGA_VCC: COUT1.1 COUT2.1 COUT3.1 COUT4.1 COUT5.1 COUT6.1 COUT7.1 COUT8.1 COUT9.1 COUT10.1 COUT11.1 COUT12.1 COUT13.1 COUT14.1 COUT15.1 COUT16.1 COUT17.1 COUT18.1 COUT19.1 COUT20.1 COUT21.1 COUT22.1 COUT23.1 COUT24.1 COUT25.1 COUT26.1 COUT27.1 COUT28.1 COUT29.1 COUT30.1 COUT31.1 COUT32.1 L5.2 L6.2 L7.2 L8.2 ; also on sheet 23 39 42
FPGA_VCC_GND: C712.2 C730.2 C748.2 C766.2 R572.1 R580.1 R588.1 R596.1 ST8.2 ST9.2 ST10.2 ST11.2 ; also on sheet 42
FPGA_VCC_HSSI_GND: C784.2 R604.1 ST14.2
FPGA_VCC_HSSI_GNDSENSE: R6900.2 ; also on sheet 42
FPGA_VCC_HSSI_GXF: COUT33.1 COUT34.1 COUT35.1 COUT36.1 COUT37.1 COUT39.1 L9.2 R6899.1 ; also on sheet 23 39
FPGA_VCC_HSSI_SENSE: R6899.2 ; also on sheet 42
IREF: C711.2 C712.1 C729.2 C730.1 C747.2 C748.1 C765.2 C766.1 C783.2 C784.1 R573.2 R581.2 R589.2 R597.2 R605.2 ; also on sheet 42
ISENSE0: C711.1 R572.2 R573.1 U62.33(ISNS1) ; also on sheet 42
ISENSE1: C783.1 R604.2 R605.1 U66.33(ISNS1) ; also on sheet 42
ISENSE2: C729.1 R580.2 R581.1 U63.33(ISNS1) ; also on sheet 42
ISENSE3: C747.1 R588.2 R589.1 U64.33(ISNS1) ; also on sheet 42
ISENSE4: C765.1 R596.2 R597.1 U65.33(ISNS1) ; also on sheet 42
PWM0: R574.2 ; also on sheet 42
PWM1: R606.2 ; also on sheet 42
PWM2: R582.2 ; also on sheet 42
PWM3: R590.2 ; also on sheet 42
PWM4: R598.2 ; also on sheet 42
SW0: L5.1 U62.1(SW1) U62.2(SW1) U62.3(SW1) U62.4(SW1) U62.5(SW1) U62.6(SW1) U62.10(SW2) U62.11(SW2) U62.12(SW2) U62.13(SW2) U62.14(SW2) U62.15(SW2) U62.16(SW2) U62.42(SW1)
SW1: L9.1 U66.1(SW1) U66.2(SW1) U66.3(SW1) U66.4(SW1) U66.5(SW1) U66.6(SW1) U66.10(SW2) U66.11(SW2) U66.12(SW2) U66.13(SW2) U66.14(SW2) U66.15(SW2) U66.16(SW2) U66.42(SW1)
SW2: L6.1 U63.1(SW1) U63.2(SW1) U63.3(SW1) U63.4(SW1) U63.5(SW1) U63.6(SW1) U63.10(SW2) U63.11(SW2) U63.12(SW2) U63.13(SW2) U63.14(SW2) U63.15(SW2) U63.16(SW2) U63.42(SW1)
SW3: L7.1 U64.1(SW1) U64.2(SW1) U64.3(SW1) U64.4(SW1) U64.5(SW1) U64.6(SW1) U64.10(SW2) U64.11(SW2) U64.12(SW2) U64.13(SW2) U64.14(SW2) U64.15(SW2) U64.16(SW2) U64.42(SW1)
SW4: L8.1 U65.1(SW1) U65.2(SW1) U65.3(SW1) U65.4(SW1) U65.5(SW1) U65.6(SW1) U65.10(SW2) U65.11(SW2) U65.12(SW2) U65.13(SW2) U65.14(SW2) U65.15(SW2) U65.16(SW2) U65.42(SW1)
TSNS0: C708.1 C722.1 C742.1 C762.1 U62.22(TMON) U63.22(TMON) U64.22(TMON) U65.22(TMON) ; also on sheet 42
TSNS1: C774.1 U66.22(TMON) ; also on sheet 42
N1965215: R591.2 R594.2 U65.34(FLTB1)
N1965219: R592.2 R595.2 U65.32(RUN1)
N1965255: C764.1 R593.2 R594.1 R595.1 U65.30(VCC)
N1965465: R598.1 U65.35(PWM1)
N1965499: C767.1 U65.36(TDIO)
N1980839: R583.2 R586.2 U64.34(FLTB1)
N1980841: R584.2 R587.2 U64.32(RUN1)
N1980849: C746.1 R585.2 R586.1 R587.1 U64.30(VCC)
N1980893: R590.1 U64.35(PWM1)
N1980897: C749.1 U64.36(TDIO)
N1982757: R575.2 R578.2 U63.34(FLTB1)
N1982759: R576.2 R579.2 U63.32(RUN1)
N1982767: C728.1 R577.2 R578.1 R579.1 U63.30(VCC)
N1982811: R582.1 U63.35(PWM1)
N1982815: C731.1 U63.36(TDIO)
N1984675: R567.2 R570.2 U62.34(FLTB1)
N1984677: R568.2 R571.2 U62.32(RUN1)
N1984685: C710.1 R569.2 R570.1 R571.1 U62.30(VCC)
N1984729: R574.1 U62.35(PWM1)
N1984733: C713.1 U62.36(TDIO)
N2171307: R599.2 R602.2 U66.34(FLTB1)
N2171311: R600.2 R603.2 U66.32(RUN1)
N2171371: C782.1 R601.2 R602.1 R603.1 U66.30(VCC)
N2171693: R606.1 U66.35(PWM1)
N2171731: C785.1 U66.36(TDIO)

Not connected (* = marked no-connect by the designer): U62 23(NC4)* 24(NC3)* 25(NC2)* 26(NC1)*; U63 23(NC4)* 24(NC3)* 25(NC2)* 26(NC1)*; U64 23(NC4)* 24(NC3)* 25(NC2)* 26(NC1)*; U65 23(NC4)* 24(NC3)* 25(NC2)* 26(NC1)*; U66 23(NC4)* 24(NC3)* 25(NC2)* 26(NC1)*

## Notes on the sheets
sheet 43
- 0.8V +/-3%
- 0.08A
sheet 44
- 0.8V +/-3%
- 0.08A
sheet 45
- 0.8V +/-3%
- 0.08A
- For 4+1, R589=499, R590=0
  For 3+1, R589=0, R590=DNI
sheet 46
- 0.8V +/-3%
- 0.08A
sheet 47
- Route SENSE lines as diff pairs from FPGA back to controller
- 0.8V +/-3%
- 0.08A
